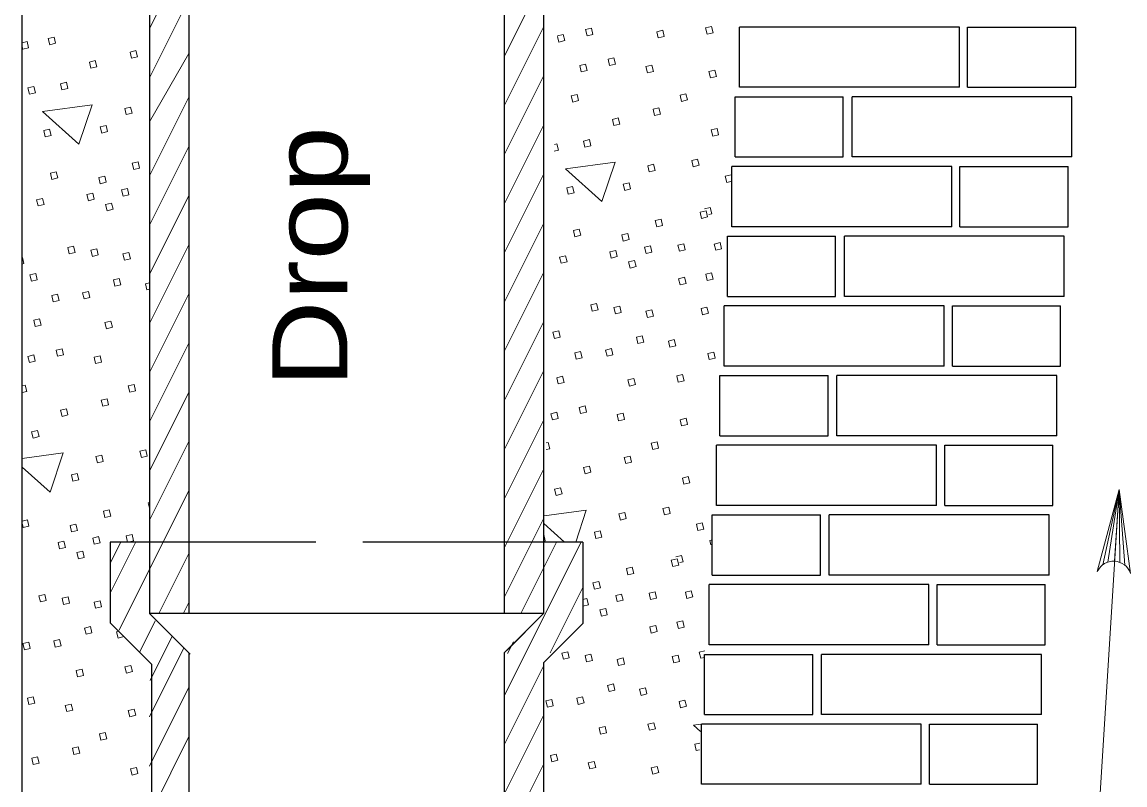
# Model space of a CAD drawing. Extents: x 750.7 to 784.7, y 860.1 to 882.1.
# Drawn here: x 760.591 to 762.937, y 868.379 to 870.002 of the extents above; entities that cross this region are included whole.
import ezdxf

# ---------------------------------------------------------------- set-up
doc = ezdxf.new("R2010")
doc.units = 0
doc.header["$LTSCALE"] = 0.064
doc.linetypes.add('LONG_DASHED', pattern=[7.5, 6, -1.5])
doc.layers.add('1', color=7, linetype='Continuous', lineweight=13)

msp = doc.modelspace()

# ---------------------------------------------------------------- linework, layer by layer
at = {"layer": '1', "lineweight": 25}
for p, q in [((760.59067, 862.95208), (760.59067, 875.03808)), ((760.94567, 870.25925), (760.94567, 868.74475)), ((761.61633, 870.25925), (761.61633, 868.74333)), ((760.862, 870.2395), (760.862, 868.74367)), ((761.7, 870.238), (761.7, 868.74367)), ((762.83242, 869.86342), (762.83242, 869.9915)), ((762.60225, 869.86342), (762.83242, 869.86342)), ((762.33775, 869.71517), (762.33775, 869.84325)), ((762.10758, 869.71517), (762.33775, 869.71517)), ((762.81617, 869.56692), (762.81617, 869.69492)), ((762.58608, 869.56692), (762.81617, 869.56692)), ((762.3215, 869.41858), (762.3215, 869.54667)), ((762.09142, 869.41858), (762.3215, 869.41858)), ((762.8, 869.27033), (762.8, 869.39842)), ((762.56983, 869.27033), (762.8, 869.27033)), ((762.30533, 869.12208), (762.30533, 869.25017)), ((762.07517, 869.12208), (762.30533, 869.12208)), ((762.78375, 868.97383), (762.78375, 869.10192)), ((762.28908, 868.82558), (762.28908, 868.95358)), ((762.55367, 868.97383), (762.78375, 868.97383)), ((760.862, 868.896), (760.77825, 868.896)), ((760.862, 868.896), (760.77825, 868.896)), ((760.862, 868.896), (760.77825, 868.896)), ((760.77825, 868.896), (760.77825, 868.72392)), ((761.78367, 868.896), (761.7, 868.896)), ((761.78367, 868.896), (761.7, 868.896)), ((761.78367, 868.896), (761.7, 868.896)), ((761.78367, 868.896), (761.78367, 868.72233)), ((761.78367, 868.896), (761.78367, 868.72233)), ((761.78367, 868.896), (761.78367, 868.72233)), ((762.059, 868.82558), (762.28908, 868.82558)), ((762.76758, 868.67733), (762.76758, 868.80533)), ((761.7, 868.74367), (760.862, 868.74367)), ((761.7, 868.74367), (760.862, 868.74367)), ((760.862, 868.74367), (760.94567, 868.65992)), ((761.7, 868.74367), (760.862, 868.74367)), ((760.862, 868.74367), (760.94833, 868.65725)), ((761.7, 868.74367), (761.61633, 868.66)), ((761.7, 868.74367), (761.62242, 868.666)), ((760.77825, 868.72392), (760.86583, 868.63633)), ((761.78367, 868.72233), (761.7, 868.63867)), ((761.78367, 868.72233), (761.71142, 868.65008)), ((762.53742, 868.67733), (762.76758, 868.67733)), ((760.94567, 868.65992), (760.94567, 867.17508)), ((761.61633, 868.66), (761.61633, 867.17533)), ((762.27292, 868.529), (762.27292, 868.65708)), ((760.86583, 868.63633), (760.86583, 867.17267)), ((761.7, 868.63867), (761.7, 867.174)), ((762.04275, 868.529), (762.27292, 868.529)), ((762.75133, 868.38075), (762.75133, 868.50883)), ((762.52125, 868.38075), (762.75133, 868.38075))]:
    msp.add_line(p, q, dxfattribs=at)
at = {"layer": '1'}
for p, q in [((760.862, 869.98858), (760.94567, 870.15592)), ((761.61633, 869.92867), (761.7, 870.09608)), ((760.862, 869.88392), (760.94567, 870.05133)), ((761.61633, 869.82408), (761.7, 869.9915)), ((761.72975, 869.973), (761.742, 869.97592)), ((760.59067, 869.95817), (760.60142, 869.96067)), ((760.862, 869.79), (760.94567, 869.93558)), ((761.61633, 869.7195), (761.7, 869.88692)), ((760.862, 869.67475), (760.94567, 869.84217)), ((761.61633, 869.61492), (761.7, 869.78225)), ((760.862, 869.57017), (760.94567, 869.7375)), ((761.72342, 869.742), (761.7285, 869.74317)), ((761.61633, 869.51025), (761.7, 869.67767)), ((762.09917, 869.67742), (762.09933, 869.67683)), ((760.862, 869.4655), (760.94567, 869.63292)), ((762.04283, 869.60492), (762.05492, 869.60783)), ((761.61633, 869.40567), (761.7, 869.57308)), ((760.862, 869.36092), (760.94567, 869.52833)), ((760.59067, 869.5015), (760.59142, 869.50167)), ((761.61633, 869.30108), (761.7, 869.4685)), ((760.862, 869.25633), (760.94567, 869.42375)), ((761.61633, 869.1965), (761.7, 869.36383)), ((760.862, 869.15175), (760.94567, 869.31908)), ((761.61633, 869.09183), (761.7, 869.25925)), ((760.59067, 869.22808), (760.59758, 869.22975)), ((760.862, 869.04708), (760.94567, 869.2145)), ((761.61633, 868.98725), (761.7, 869.15467)), ((760.862, 868.9425), (760.94567, 869.10992)), ((761.70583, 869.10675), (761.71025, 869.10783)), ((760.67833, 869.08542), (760.59067, 869.07375)), ((761.61633, 868.88267), (761.7, 869.05008)), ((760.79708, 868.70817), (760.94567, 869.00533)), ((762.84308, 867.71025), (762.92467, 869.00808)), ((762.88975, 868.84775), (762.92467, 869.00808)), ((762.9005, 868.85325), (762.92467, 869.00808)), ((762.91508, 868.85517), (762.92467, 869.00808)), ((762.92625, 868.85275), (762.92467, 869.00808)), ((762.937, 868.84667), (762.92467, 869.00808)), ((761.791, 868.9635), (761.70158, 868.95158)), ((761.7685, 868.896), (761.791, 868.9635)), ((760.59067, 868.9405), (760.60217, 868.94325)), ((761.61633, 868.77808), (761.7, 868.94542)), ((761.70108, 868.93542), (761.745, 868.896)), ((761.70042, 868.91167), (761.70067, 868.91175)), ((760.77825, 868.85075), (760.80092, 868.896)), ((760.77925, 868.79), (760.83258, 868.89675)), ((761.61633, 868.56883), (761.77992, 868.896)), ((761.6515, 868.74383), (761.72758, 868.896)), ((760.88158, 868.74367), (760.94567, 868.87175)), ((760.88158, 868.74367), (760.94567, 868.87175)), ((761.9815, 868.86433), (761.99358, 868.86717)), ((761.71425, 868.66017), (761.78367, 868.799)), ((760.93433, 868.7445), (760.94567, 868.76717)), ((760.93433, 868.7445), (760.94567, 868.76717)), ((761.78367, 868.77383), (761.79242, 868.77592)), ((760.84092, 868.66233), (760.87408, 868.72867)), ((760.84092, 868.66233), (760.87408, 868.72867)), ((760.86292, 868.60158), (760.90925, 868.69442)), ((760.86783, 868.61142), (760.90925, 868.69442)), ((760.862, 868.52408), (760.93517, 868.67058)), ((761.62358, 868.65892), (761.636, 868.68375)), ((761.61633, 868.46425), (761.7, 868.63167)), ((760.862, 868.4195), (760.94567, 868.58692)), ((761.61633, 868.35967), (761.7, 868.527)), ((760.862, 868.31492), (760.94567, 868.48225)), ((761.61633, 868.255), (761.7, 868.42242))]:
    msp.add_line(p, q, dxfattribs=at)
at = {"layer": '1', "linetype": 'LONG_DASHED', "lineweight": 25}
msp.add_line((761.7, 868.896), (760.862, 868.896), dxfattribs=at)
msp.add_line((761.7, 868.896), (760.862, 868.896), dxfattribs=at)
msp.add_line((761.7, 868.896), (760.862, 868.896), dxfattribs=at)
at = {"layer": '1'}
for points in [[(761.80208, 869.98925), (761.80533, 869.976), (761.79275, 869.973), (761.78958, 869.98625)], [(761.95358, 869.98467), (761.95675, 869.97142), (761.94425, 869.96842), (761.941, 869.98167)], [(762.05742, 869.99283), (762.06067, 869.97958), (762.04808, 869.97658), (762.04483, 869.98983)], [(760.65892, 869.97033), (760.66208, 869.95708), (760.64958, 869.95408), (760.64633, 869.96733)], [(760.83292, 869.9415), (760.83617, 869.92833), (760.82358, 869.92533), (760.82042, 869.9385)], [(760.74642, 869.92017), (760.74958, 869.90692), (760.73708, 869.90392), (760.73383, 869.91717)], [(761.84983, 869.926), (761.853, 869.91275), (761.84042, 869.90975), (761.83725, 869.923)], [(761.78967, 869.91258), (761.79283, 869.89933), (761.78033, 869.89633), (761.77708, 869.90958)], [(761.93058, 869.91058), (761.93375, 869.89733), (761.92117, 869.89433), (761.918, 869.90758)], [(762.06458, 869.89983), (762.06783, 869.88658), (762.05525, 869.88358), (762.052, 869.89683)], [(760.685, 869.87417), (760.68817, 869.86092), (760.67558, 869.85792), (760.67242, 869.87117)], [(760.61583, 869.86517), (760.619, 869.85192), (760.6065, 869.84892), (760.60325, 869.86217)], [(761.77158, 869.84842), (761.77483, 869.83517), (761.76225, 869.83217), (761.759, 869.84542)], [(762.00317, 869.84983), (762.00633, 869.83658), (761.99375, 869.83358), (761.99058, 869.84683)], [(760.73958, 869.826), (760.63417, 869.812), (760.71175, 869.74233)], [(760.82158, 869.8215), (760.82475, 869.80825), (760.81225, 869.80525), (760.809, 869.8185)], [(761.85908, 869.79817), (761.86225, 869.78492), (761.84975, 869.78192), (761.8465, 869.79517)], [(761.94567, 869.81958), (761.94883, 869.80633), (761.93625, 869.80333), (761.93308, 869.81658)], [(760.64933, 869.77425), (760.65258, 869.761), (760.64, 869.758), (760.63675, 869.77125)], [(760.7695, 869.78233), (760.77275, 869.76908), (760.76017, 869.76608), (760.757, 869.77933)], [(762.06942, 869.77575), (762.07258, 869.7625), (762.06008, 869.7595), (762.05683, 869.77275)], [(761.79767, 869.75217), (761.80083, 869.73892), (761.78825, 869.736), (761.78508, 869.74917)], [(760.83758, 869.705), (760.84083, 869.69175), (760.82825, 869.68875), (760.82508, 869.702)], [(761.85233, 869.70408), (761.74683, 869.69), (761.82442, 869.62033)], [(762.02792, 869.71075), (762.03108, 869.6975), (762.01858, 869.69458), (762.01533, 869.70775)], [(760.6635, 869.68383), (760.66667, 869.67058), (760.65408, 869.66758), (760.65092, 869.68083)], [(761.93425, 869.69958), (761.93742, 869.68633), (761.92492, 869.68333), (761.92167, 869.69658)], [(760.7665, 869.67458), (760.76975, 869.66133), (760.75717, 869.65833), (760.754, 869.67158)], [(761.88217, 869.66033), (761.88542, 869.64708), (761.87283, 869.64408), (761.86967, 869.65733)], [(760.74108, 869.63842), (760.74425, 869.62525), (760.73167, 869.62225), (760.7285, 869.6355)], [(760.81492, 869.648), (760.81808, 869.63475), (760.80558, 869.63175), (760.80233, 869.645)], [(761.762, 869.65233), (761.76525, 869.63908), (761.75267, 869.63608), (761.7495, 869.64933)], [(760.63425, 869.62717), (760.6375, 869.61392), (760.62492, 869.61092), (760.62175, 869.62417)], [(760.78108, 869.61717), (760.78425, 869.60392), (760.77175, 869.60092), (760.7685, 869.61417)], [(762.04583, 869.60092), (762.049, 869.58767), (762.03642, 869.58467), (762.03325, 869.59792)], [(761.95033, 869.583), (761.9535, 869.56975), (761.94092, 869.56675), (761.93775, 869.58)], [(761.77617, 869.56183), (761.77933, 869.54858), (761.76675, 869.54558), (761.76358, 869.55883)], [(761.87917, 869.55258), (761.88242, 869.53933), (761.86983, 869.53633), (761.86667, 869.54958)], [(760.70042, 869.52533), (760.70358, 869.51208), (760.69108, 869.50908), (760.68783, 869.52233)], [(760.74975, 869.51992), (760.75292, 869.50667), (760.74042, 869.50367), (760.73717, 869.51692)], [(761.85375, 869.5165), (761.85692, 869.50325), (761.84433, 869.50025), (761.84117, 869.5135)], [(761.92758, 869.526), (761.93075, 869.51283), (761.91825, 869.50983), (761.915, 869.52308)], [(761.99858, 869.53067), (762.00175, 869.51742), (761.98925, 869.5145), (761.986, 869.52767)], [(762.07575, 869.533), (762.07892, 869.51975), (762.06633, 869.51675), (762.06317, 869.53)], [(760.81783, 869.51183), (760.82108, 869.49867), (760.8085, 869.49567), (760.80533, 869.50892)], [(761.74692, 869.50517), (761.75017, 869.492), (761.73758, 869.489), (761.73442, 869.50225)], [(761.89375, 869.49525), (761.89692, 869.482), (761.88442, 869.479), (761.88117, 869.49225)], [(762.05767, 869.46875), (762.06083, 869.4555), (762.04825, 869.45258), (762.04508, 869.46575)], [(760.61992, 869.46733), (760.62308, 869.45408), (760.61058, 869.45108), (760.60733, 869.46433)], [(760.79742, 869.45658), (760.80067, 869.44333), (760.78808, 869.44042), (760.78492, 869.45358)], [(762.00017, 869.45917), (762.00333, 869.44592), (761.99075, 869.44292), (761.98758, 869.45617)], [(760.66642, 869.42342), (760.66958, 869.41017), (760.657, 869.40717), (760.65383, 869.42042)], [(760.73192, 869.42933), (760.73508, 869.41608), (760.72258, 869.41308), (760.71933, 869.42633)], [(761.81308, 869.40333), (761.81625, 869.39008), (761.80375, 869.38708), (761.8005, 869.40033)], [(761.86242, 869.39792), (761.86558, 869.38467), (761.85308, 869.38167), (761.84983, 869.39492)], [(761.93058, 869.38992), (761.93375, 869.37667), (761.92117, 869.37367), (761.918, 869.38692)], [(762.04783, 869.39583), (762.051, 869.38258), (762.03842, 869.37958), (762.03525, 869.39283)], [(760.62808, 869.37067), (760.63133, 869.35742), (760.61875, 869.35442), (760.61558, 869.36767)], [(760.77958, 869.36608), (760.78283, 869.35283), (760.77025, 869.34983), (760.767, 869.36308)], [(761.73258, 869.34542), (761.73575, 869.33217), (761.72325, 869.32917), (761.72, 869.34242)], [(761.91008, 869.33467), (761.91333, 869.32142), (761.90075, 869.31842), (761.89758, 869.33167)], [(760.67583, 869.30733), (760.679, 869.29408), (760.66642, 869.29108), (760.66325, 869.30433)], [(761.84458, 869.30742), (761.84775, 869.29417), (761.83525, 869.29117), (761.832, 869.30442)], [(761.97825, 869.32658), (761.98142, 869.31333), (761.96883, 869.31042), (761.96567, 869.32358)], [(760.61567, 869.294), (760.61883, 869.28075), (760.60633, 869.27775), (760.60308, 869.291)], [(760.75658, 869.29192), (760.75975, 869.27875), (760.74725, 869.27575), (760.744, 869.289)], [(761.77908, 869.30142), (761.78225, 869.28817), (761.76967, 869.28517), (761.7665, 869.29842)], [(762.06225, 869.30025), (762.06542, 869.28708), (762.05283, 869.28408), (762.04967, 869.29733)], [(761.74075, 869.24867), (761.744, 869.23542), (761.73142, 869.23242), (761.72825, 869.24567)], [(761.89225, 869.24408), (761.8955, 869.23083), (761.88292, 869.22783), (761.87975, 869.24108)], [(761.99608, 869.25225), (761.99933, 869.239), (761.98675, 869.236), (761.98358, 869.24925)], [(760.82917, 869.23125), (760.83233, 869.218), (760.81975, 869.215), (760.81658, 869.22825)], [(760.77167, 869.20092), (760.77483, 869.18767), (760.76225, 869.18475), (760.75908, 869.19792)], [(760.68508, 869.17958), (760.68825, 869.16633), (760.67575, 869.16333), (760.6725, 869.17658)], [(761.72833, 869.172), (761.7315, 869.15875), (761.719, 869.15575), (761.71575, 869.169)], [(761.7885, 869.18542), (761.79167, 869.17217), (761.77908, 869.16917), (761.77592, 869.18242)], [(761.86925, 869.17), (761.87242, 869.15675), (761.85992, 869.15375), (761.85667, 869.167)], [(762.00325, 869.15925), (762.0065, 869.146), (761.99392, 869.143), (761.99075, 869.15625)], [(760.62367, 869.13358), (760.62683, 869.12033), (760.61433, 869.11733), (760.61108, 869.13058)], [(761.94183, 869.10925), (761.945, 869.096), (761.93242, 869.093), (761.92925, 869.10625)], [(760.76025, 869.08092), (760.76342, 869.06767), (760.75092, 869.06467), (760.74767, 869.07792)], [(760.85392, 869.09217), (760.85708, 869.07892), (760.84458, 869.07592), (760.84133, 869.08917)], [(761.88433, 869.079), (761.8875, 869.06575), (761.87492, 869.06275), (761.87175, 869.076)], [(761.79775, 869.05758), (761.801, 869.04433), (761.78842, 869.04133), (761.78517, 869.05458)], [(760.70825, 869.04175), (760.71142, 869.0285), (760.69883, 869.0255), (760.69567, 869.03875)], [(762.00808, 869.03517), (762.01125, 869.02192), (761.99875, 869.01892), (761.9955, 869.03217)], [(761.73633, 869.01158), (761.7395, 868.99833), (761.727, 868.99533), (761.72375, 869.00858)], [(760.77633, 868.96442), (760.7795, 868.95117), (760.76692, 868.94817), (760.76375, 868.96142)], [(761.87292, 868.959), (761.87608, 868.94575), (761.86358, 868.94275), (761.86033, 868.956)], [(761.96658, 868.97017), (761.96983, 868.95692), (761.95725, 868.95392), (761.954, 868.96717)], [(760.70517, 868.934), (760.70842, 868.92075), (760.69583, 868.91775), (760.69267, 868.931)], [(762.03783, 868.93683), (762.041, 868.92358), (762.0285, 868.92058), (762.02525, 868.93383)], [(760.75358, 868.90742), (760.75683, 868.89417), (760.74425, 868.89117), (760.74108, 868.90442)], [(761.82092, 868.91975), (761.82408, 868.9065), (761.8115, 868.9035), (761.80833, 868.91675)], [(760.67975, 868.89783), (760.68292, 868.88467), (760.67033, 868.88167), (760.66717, 868.89492)], [(760.71975, 868.87658), (760.72292, 868.86333), (760.71042, 868.86033), (760.70717, 868.87358)], [(761.9845, 868.86033), (761.98767, 868.84708), (761.97517, 868.84408), (761.97192, 868.85733)], [(761.889, 868.84242), (761.89217, 868.82917), (761.87958, 868.82617), (761.87642, 868.83942)], [(761.81792, 868.812), (761.82108, 868.79875), (761.8085, 868.79575), (761.80533, 868.809)], [(761.93725, 868.79008), (761.94042, 868.77683), (761.92792, 868.77383), (761.92467, 868.78708)], [(762.01442, 868.79242), (762.01758, 868.77917), (762.005, 868.77617), (762.00183, 868.78942)], [(760.63908, 868.78467), (760.64225, 868.7715), (760.62975, 868.7685), (760.6265, 868.78175)], [(760.68842, 868.77933), (760.69158, 868.76608), (760.67908, 868.76308), (760.67583, 868.77633)], [(760.75658, 868.77125), (760.75975, 868.75808), (760.74717, 868.75508), (760.744, 868.76825)], [(761.86625, 868.78542), (761.8695, 868.77217), (761.85692, 868.76925), (761.85375, 868.78242)], [(761.83242, 868.75458), (761.83567, 868.74142), (761.82308, 868.73842), (761.81992, 868.75167)], [(761.93883, 868.71858), (761.942, 868.70533), (761.92942, 868.70233), (761.92625, 868.71558)], [(761.99633, 868.72817), (761.9995, 868.71492), (761.987, 868.71192), (761.98375, 868.72517)], [(760.73608, 868.716), (760.73933, 868.70275), (760.72675, 868.69975), (760.72358, 868.713)], [(760.60508, 868.68283), (760.60825, 868.66958), (760.59575, 868.66658), (760.5925, 868.67983)], [(760.67058, 868.68875), (760.67375, 868.6755), (760.66125, 868.6725), (760.658, 868.68575)], [(761.75175, 868.66275), (761.75492, 868.6495), (761.74242, 868.6465), (761.73917, 868.65975)], [(761.80108, 868.65733), (761.80425, 868.64408), (761.79175, 868.64108), (761.7885, 868.65433)], [(761.86925, 868.64933), (761.87242, 868.63608), (761.85983, 868.63308), (761.85667, 868.64633)], [(761.9865, 868.65525), (761.98967, 868.642), (761.97717, 868.639), (761.97392, 868.65225)], [(760.71825, 868.6255), (760.7215, 868.61225), (760.70892, 868.60925), (760.70575, 868.6225)], [(760.82208, 868.63358), (760.82533, 868.62033), (760.81275, 868.61733), (760.80958, 868.63058)], [(761.84875, 868.59408), (761.852, 868.58083), (761.83942, 868.57783), (761.83625, 868.59108)], [(761.91692, 868.586), (761.92008, 868.57275), (761.90758, 868.56983), (761.90433, 868.583)], [(760.6145, 868.56675), (760.61767, 868.5535), (760.60508, 868.5505), (760.60192, 868.56375)], [(761.71775, 868.56083), (761.72092, 868.54758), (761.70842, 868.54458), (761.70517, 868.55783)], [(761.78325, 868.56683), (761.78642, 868.55358), (761.77392, 868.55058), (761.77067, 868.56383)], [(762.00092, 868.55967), (762.00408, 868.5465), (761.99158, 868.5435), (761.98833, 868.55675)], [(760.69525, 868.55133), (760.69842, 868.53808), (760.68592, 868.53517), (760.68267, 868.54833)], [(760.82925, 868.54058), (760.8325, 868.52733), (760.81992, 868.52442), (760.81675, 868.53758)], [(761.93475, 868.51167), (761.938, 868.49842), (761.92542, 868.49542), (761.92225, 868.50867)], [(760.76783, 868.49067), (760.771, 868.47742), (760.75842, 868.47442), (760.75525, 868.48767)], [(761.83092, 868.5035), (761.83417, 868.49025), (761.82158, 868.48725), (761.81842, 868.5005)], [(760.71033, 868.46033), (760.7135, 868.44708), (760.70092, 868.44408), (760.69775, 868.45733)], [(760.62375, 868.439), (760.627, 868.42575), (760.61442, 868.42275), (760.61125, 868.436)], [(761.72717, 868.44483), (761.73033, 868.43158), (761.71775, 868.42858), (761.71458, 868.44183)], [(760.83408, 868.4165), (760.83733, 868.40333), (760.82475, 868.40033), (760.8215, 868.41358)], [(761.80792, 868.42942), (761.81108, 868.41617), (761.79858, 868.41317), (761.79533, 868.42642)], [(761.94192, 868.41867), (761.94517, 868.40542), (761.93258, 868.40242), (761.92942, 868.41567)]]:
    msp.add_lwpolyline(points, close=True, dxfattribs=at)
at = {"layer": '1', "lineweight": 25}
for points in [[(762.58475, 869.86342), (762.58475, 869.9915), (762.117, 869.9915)], [(762.58475, 869.86342), (762.117, 869.86342), (762.117, 869.9915)], [(762.60225, 869.86342), (762.60225, 869.9915), (762.83242, 869.9915)], [(762.10758, 869.71517), (762.10758, 869.84325), (762.33775, 869.84325)], [(762.82433, 869.71517), (762.82433, 869.84325), (762.35658, 869.84325)], [(762.82433, 869.71517), (762.35658, 869.71517), (762.35658, 869.84325)], [(762.5685, 869.56692), (762.5685, 869.69492), (762.10083, 869.69492)], [(762.5685, 869.56692), (762.10083, 869.56692), (762.10083, 869.69492)], [(762.58608, 869.56692), (762.58608, 869.69492), (762.81617, 869.69492)], [(762.09142, 869.41858), (762.09142, 869.54667), (762.3215, 869.54667)], [(762.80808, 869.41867), (762.80808, 869.54667), (762.34042, 869.54667)], [(762.80808, 869.41867), (762.34042, 869.41867), (762.34042, 869.54667)], [(762.55233, 869.27033), (762.55233, 869.39842), (762.08458, 869.39842)], [(762.55233, 869.27033), (762.08458, 869.27033), (762.08458, 869.39842)], [(762.56983, 869.27033), (762.56983, 869.39842), (762.8, 869.39842)], [(762.07517, 869.12208), (762.07517, 869.25017), (762.30533, 869.25017)], [(762.79192, 869.12208), (762.79192, 869.25017), (762.32417, 869.25017)], [(762.79192, 869.12208), (762.32417, 869.12208), (762.32417, 869.25017)], [(762.53608, 868.97383), (762.53608, 869.10192), (762.06842, 869.10192)], [(762.53608, 868.97383), (762.06842, 868.97383), (762.06842, 869.10192)], [(762.55367, 868.97383), (762.55367, 869.10192), (762.78375, 869.10192)], [(762.059, 868.82558), (762.059, 868.95358), (762.28908, 868.95358)], [(762.77567, 868.82558), (762.77567, 868.95358), (762.308, 868.95358)], [(762.77567, 868.82558), (762.308, 868.82558), (762.308, 868.95358)], [(762.51992, 868.67733), (762.51992, 868.80533), (762.05217, 868.80533)], [(762.51992, 868.67733), (762.05217, 868.67733), (762.05217, 868.80533)], [(762.53742, 868.67733), (762.53742, 868.80533), (762.76758, 868.80533)], [(762.04275, 868.529), (762.04275, 868.65708), (762.27292, 868.65708)], [(762.7595, 868.529), (762.7595, 868.65708), (762.29175, 868.65708)], [(762.7595, 868.529), (762.29175, 868.529), (762.29175, 868.65708)], [(762.50367, 868.38075), (762.50367, 868.50883), (762.036, 868.50883)], [(762.50367, 868.38075), (762.036, 868.38075), (762.036, 868.50883)], [(762.52125, 868.38075), (762.52125, 868.50883), (762.75133, 868.50883)]]:
    msp.add_lwpolyline(points, dxfattribs=at)
at = {"layer": '1'}
for points in [[(761.742, 869.97592), (761.74517, 869.96267), (761.73258, 869.95967), (761.72975, 869.9715)], [(760.60142, 869.96067), (760.60458, 869.9475), (760.59208, 869.9445), (760.59067, 869.95017)], [(761.7285, 869.74317), (761.73167, 869.72992), (761.723, 869.72783)], [(762.09858, 869.66333), (762.08983, 869.66117), (762.08658, 869.67442), (762.09917, 869.67742)], [(762.05492, 869.60783), (762.05808, 869.59458), (762.05175, 869.593)], [(760.59142, 869.50167), (760.59458, 869.4885), (760.59067, 869.4875)], [(760.862, 869.43375), (760.85617, 869.43233), (760.853, 869.44558), (760.862, 869.44775)], [(760.59758, 869.22975), (760.60083, 869.2165), (760.59067, 869.21408)], [(761.71025, 869.10783), (761.7135, 869.09458), (761.70542, 869.09267)], [(760.59067, 869.05542), (760.65042, 869.00175), (760.67833, 869.08542)], [(760.59067, 869.02275), (760.59125, 869.02042), (760.59067, 869.02033)], [(762.87825, 868.83358), (762.92467, 869.00808), (762.94892, 868.82908)], [(760.862, 868.96808), (760.85925, 868.97933), (760.862, 868.97992)], [(760.60217, 868.94325), (760.60533, 868.93), (760.59283, 868.927), (760.59067, 868.93583)], [(760.81517, 868.896), (760.812, 868.90908), (760.82458, 868.91208)], [(760.82458, 868.91208), (760.82775, 868.89883), (760.81592, 868.896)], [(761.70067, 868.91175), (761.70392, 868.8985), (761.70008, 868.89758)], [(762.056, 868.89033), (762.05375, 868.8995), (762.0565, 868.90017)], [(761.99358, 868.86717), (761.99683, 868.854), (761.99042, 868.85242)], [(761.79242, 868.77592), (761.79558, 868.76267), (761.78367, 868.75983)], [(760.80742, 868.69475), (760.79492, 868.69175), (760.79167, 868.705), (760.79608, 868.70608)], [(762.04275, 868.65058), (762.03467, 868.64867), (762.03142, 868.66192), (762.04358, 868.66483)], [(762.035, 868.50867), (762.01925, 868.50658), (762.03408, 868.49325)], [(762.032, 868.45425), (762.02508, 868.45258), (762.02192, 868.46583), (762.03275, 868.46842)]]:
    msp.add_lwpolyline(points, dxfattribs=at)
msp.add_arc((762.91273, 868.81706), 0.03822, 18.49101, 154.31714, dxfattribs=at)

# ---------------------------------------------------------------- texts
at = {"layer": '1', "width": 1.2}
msp.add_text('Drop', height=0.16, rotation=90, dxfattribs=at).set_placement((761.28292, 869.22442))

doc.saveas('drawing.dxf')
